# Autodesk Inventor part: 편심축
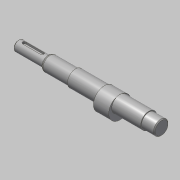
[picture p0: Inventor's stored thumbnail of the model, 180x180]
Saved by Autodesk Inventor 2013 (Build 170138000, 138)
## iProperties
Created: 2017-08
Part Number: 편심축
Material: 강철, 연강
Document SubType Name: Modeling
Designer: mduedu
Density: 1 g/cm^3
Author: mduedu
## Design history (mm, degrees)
sketch "스케치1"
  geometry: L1 (0, 0)-(168, 0); L2 (168, 0)-(168, 8.5); L3 (168, 8.5)-(153, 8.5); L4 (153, 8.5)-(153, 9.5); L5 (153, 9.5)-(67, 9.5); L6 (67, 9.5)-(67, 8.5); L7 (67, 8.5)-(35, 8.5); L8 (35, 8.5)-(35, 6); L9 (35, 6)-(0, 6); L10 (0, 6)-(0, 0)
  constraints: 20 end point, 6 parallel, 2 collinear, 2 perpendicular, 1 horizontal
  dimensions: "d0" = 168 distance of L1.start L1.end; "d1" = 17 diameter of L3 L1; "d2" = 19 diameter of L5 L1; "d3" = 12 diameter of L9 L1; "d4" = 35 distance of L8.end L9.end; "d5" = 15 distance of L2.end L3.end; "d6" = 86 distance of L4.end L5.end
revolve "회전1" sketch "스케치1" stored, may be unused: angle "d7" = 90 deg
node "작업 평면1"
sketch "스케치2"
  geometry: C1 r 9.5 at (0, 0) reference; C2 r 13 at (0, -3.5); 1 further point
  constraints: 1 centre point, 1 tangent, 1 vertical alignment
  dimensions: "d8" = 3.5 distance of point (0, 0) C2.centre
extrude "돌출1" join sketch "스케치2" stored distance "d9" = 18; taper "d10" = 0 deg
chamfer "모따기1" distance "d11" = 1; stored, may be unused: second distance "d12" = 2, angle "d13" = 45 deg
node "작업 평면2"
sketch "스케치3"
  geometry: L1 (10.5, -2)-(-10.5, -2); L2 (-10.5, -2)-(-10.5, 2); L3 (-10.5, 2)-(10.5, 2); L4 (10.5, 2)-(10.5, -2); L5 (17.5, 6)-(17.5, -6) reference; L6 (-17.5, 8.5)-(-17.5, -8.5) reference; A1 r 2 centre (10.5, 0) between (10.5, -2) and (10.5, 2); A2 r 2 centre (-10.5, 0) between (-10.5, 2) and (-10.5, -2); A3 r 2 centre (10.5, 0) between (10.5, 2) and (10.5, -2); A4 r 2 centre (-10.5, 0) between (-10.5, -2) and (-10.5, 2); 1 further point
  constraints: 8 end point, 8 point on circle, 4 centre point, 2 midpoint, 2 parallel, 1 horizontal, 1 horizontal alignment, 1 perpendicular
  dimensions: "d14" = 25 dimension on A2 A1; "d16" = 4 distance between parallel lines of L3 L1; "d17" = 5 distance edge to line of A1 L5; "d46" = 5 distance edge to line of A2 L6 (derived)
extrude "돌출2" cut sketch "스케치3" distance "d18" = 2.5; taper "d19" = 0 deg
chamfer "모따기2" distance "d20" = 1; stored, may be unused: second distance "d21" = 2, angle "d22" = 45 deg
chamfer "모따기4" distance "d39" = 1.82; stored, may be unused: second distance "d40" = 2, angle "d41" = 30 deg
fillet "모깎기4" dims "d45" = 2
hole "구멍1" diameter "d29" = 3.242; stored, may be unused: countersink angle "d33" = 90 deg, drill point angle "d35" = 118 deg; dims "d30" = 8, "d31" = 4, "d32" = 2, "d34" = 10, "d36" = 10, "d37" = 10
node "솔리드1"
node "절단 모서리 투영1"
